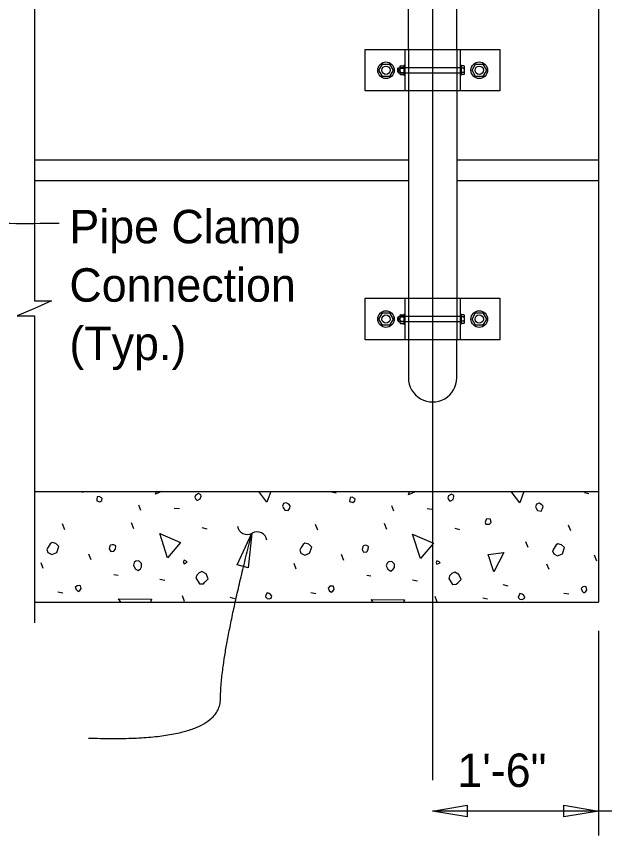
# Model space of a CAD drawing. Extents: x 0.5 to 39.7, y 0.9 to 25.6.
# Drawn here: x 23.735 to 27.279, y 12.062 to 17.001 of the extents above; entities that cross this region are included whole.
import ezdxf

# ---------------------------------------------------------------- set-up
doc = ezdxf.new("R2010")
doc.units = 0
for name, color, linetype in [('CL_Major', 7, 'Continuous'), ('Dimension', 7, 'Continuous'), ('Miscellaneous', 7, 'Continuous'), ('SteelMisc', 7, 'Continuous'), ('SteelMisc_h', 7, 'Continuous'), ('SupstrConc', 7, 'Continuous'), ('TextStructures', 7, 'Continuous')]:
    doc.layers.add(name, color=color, linetype=linetype)

msp = doc.modelspace()

# ---------------------------------------------------------------- linework, layer by layer
at = {"layer": 'CL_Major'}
msp.add_line((26.2429, 25.5043), (26.2429, 12.3953), dxfattribs=at)
at = {"layer": 'Dimension'}
for p, q in [((27.2429, 13.2961), (27.2429, 12.062)), ((28.5763, 12.21), (26.2429, 12.21))]:
    msp.add_line(p, q, dxfattribs=at)
msp.add_lwpolyline([(23.8431, 17.1361), (23.8431, 15.2855), (23.9464, 15.2855), (23.8431, 15.2405), (23.7397, 15.1955), (23.8431, 15.1955), (23.8431, 13.3448)], dxfattribs=at)
for points in [[(25.1546, 13.8857), (25.1324, 13.6757), (25.0644, 13.6947)], [(26.2429, 12.2101), (26.4512, 12.2454), (26.4512, 12.1748)], [(27.2429, 12.2101), (27.0347, 12.1748), (27.0347, 12.2454)]]:
    msp.add_lwpolyline(points, close=True, dxfattribs=at)
for centre, start, end in [((25.1255, 13.9368), 188.4294, 300.1567), ((25.1854, 13.8337), 8.4294, 120.1567)]:
    msp.add_arc(centre, 0.0596, start, end, dxfattribs=at)
for points in [[(23.9932, 15.7529), (23.0399, 15.7236), (23.3618, 16.2556), (23.4433, 16.5898), (22.9335, 16.6682), (22.6122, 16.6783)], [(24.1685, 12.6502), (24.964, 12.6205), (24.9656, 13.1567), (25.1547, 13.8855)]]:
    msp.add_open_spline(points, degree=2, dxfattribs=at)
at = {"layer": 'Miscellaneous'}
for p, q in [((26.0354, 16.6691), (26.0354, 16.6812)), ((26.0411, 16.6691), (26.0411, 16.6812)), ((26.0354, 15.1691), (26.0354, 15.1812)), ((26.0411, 15.1691), (26.0411, 15.1812)), ((24.1186, 14.1361), (24.1373, 14.1324)), ((25.6346, 14.1341), (25.6611, 14.1288)), ((27.1584, 14.1306), (27.185, 14.1253)), ((24.4856, 14.021), (24.4732, 14.0546)), ((24.6853, 14.0369), (24.7172, 14.0334)), ((26.0094, 14.0175), (25.997, 14.051)), ((26.2092, 14.0334), (26.241, 14.0298)), ((24.0277, 13.9061), (24.0136, 13.9414)), ((24.4432, 13.9114), (24.429, 13.9467)), ((25.5515, 13.9026), (25.5374, 13.9379)), ((25.967, 13.9079), (25.9528, 13.9432)), ((27.0754, 13.899), (27.0612, 13.9344)), ((24.8533, 13.9185), (24.8816, 13.9114)), ((26.3771, 13.9149), (26.4054, 13.9079)), ((26.819, 13.7983), (26.8049, 13.8336)), ((24.1851, 13.724), (24.1709, 13.7594)), ((25.7089, 13.7205), (25.6947, 13.7558)), ((27.2327, 13.7169), (27.2185, 13.7523)), ((23.8969, 13.6727), (23.8845, 13.7063)), ((25.4207, 13.6692), (25.4084, 13.7028)), ((26.9445, 13.6657), (26.9322, 13.6993)), ((24.3229, 13.6356), (24.3477, 13.6321)), ((25.8468, 13.6321), (25.8715, 13.6286)), ((24.5987, 13.6073), (24.6288, 13.602)), ((26.1225, 13.6038), (26.1526, 13.5985)), ((26.667, 13.5755), (26.6953, 13.5684)), ((23.9853, 13.5313), (24.0154, 13.526)), ((24.7472, 13.473), (24.7348, 13.5066)), ((25.0212, 13.4995), (25.0495, 13.4924)), ((25.5091, 13.5278), (25.5392, 13.5225)), ((26.271, 13.4695), (26.2587, 13.503)), ((26.545, 13.496), (26.5733, 13.4889)), ((27.0329, 13.5243), (27.063, 13.5189))]:
    msp.add_line(p, q, dxfattribs=at)
for points in [[(24.574, 14.12), (24.5789, 14.1361)], [(24.6099, 14.1361), (24.574, 14.12)], [(25.244, 14.0723), (25.1954, 14.1361)], [(25.2678, 14.1361), (25.244, 14.0723)], [(26.0978, 14.1165), (26.1038, 14.1361)], [(26.1416, 14.1361), (26.0978, 14.1165)], [(26.7678, 14.0687), (26.7165, 14.1361)], [(26.793, 14.1361), (26.7678, 14.0687)], [(24.2186, 14.0793), (24.2381, 14.074), (24.2505, 14.0829), (24.2522, 14.0952), (24.2487, 14.0988), (24.2346, 14.1058), (24.2222, 14.1041), (24.2204, 14.0917), (24.2186, 14.0793)], [(24.8215, 14.0846), (24.8285, 14.0846), (24.8427, 14.0917), (24.848, 14.1076), (24.8462, 14.1165), (24.8321, 14.1235), (24.8144, 14.1129), (24.8109, 14.1023), (24.8144, 14.0917), (24.8215, 14.0846)], [(25.7425, 14.0758), (25.7619, 14.0705), (25.7743, 14.0793), (25.7761, 14.0917), (25.7725, 14.0952), (25.7584, 14.1023), (25.746, 14.1005), (25.7442, 14.0882), (25.7425, 14.0758)], [(26.3453, 14.0811), (26.3523, 14.0811), (26.3665, 14.0882), (26.3718, 14.1041), (26.37, 14.1129), (26.3559, 14.12), (26.3382, 14.1094), (26.3347, 14.0988), (26.3382, 14.0882), (26.3453, 14.0811)], [(25.3429, 14.0404), (25.3518, 14.0245), (25.373, 14.021), (25.3818, 14.0369), (25.3854, 14.051), (25.3765, 14.0599), (25.3606, 14.0687), (25.3447, 14.0634), (25.3394, 14.0475), (25.3429, 14.0404)], [(26.8668, 14.0369), (26.8756, 14.021), (26.8968, 14.0175), (26.9057, 14.0334), (26.9092, 14.0475), (26.9004, 14.0564), (26.8844, 14.0652), (26.8685, 14.0599), (26.8632, 14.044), (26.8668, 14.0369)], [(26.5645, 13.9397), (26.5857, 13.9397), (26.5963, 13.9503), (26.591, 13.9697), (26.568, 13.9715), (26.5645, 13.9609), (26.5592, 13.9521), (26.5645, 13.9397), (26.5609, 13.9432)], [(24.6464, 13.7364), (24.5987, 13.8831), (24.7242, 13.8283), (24.6464, 13.7364)], [(26.1703, 13.7328), (26.1225, 13.8796), (26.248, 13.8248), (26.1703, 13.7328)], [(23.9252, 13.7682), (23.9482, 13.7558), (23.9782, 13.7682), (23.9906, 13.8053), (23.9729, 13.823), (23.9499, 13.8283), (23.9393, 13.8212), (23.927, 13.8018), (23.9181, 13.7859), (23.9252, 13.7682)], [(24.2947, 13.7912), (24.3035, 13.7753), (24.3229, 13.777), (24.3318, 13.7894), (24.3336, 13.8089), (24.3212, 13.8142), (24.3123, 13.8159), (24.3017, 13.8124), (24.2982, 13.8089), (24.2947, 13.7912)], [(25.449, 13.7647), (25.472, 13.7523), (25.502, 13.7647), (25.5144, 13.8018), (25.4967, 13.8195), (25.4738, 13.8248), (25.4632, 13.8177), (25.4508, 13.7983), (25.4419, 13.7823), (25.449, 13.7647)], [(25.8185, 13.7876), (25.8273, 13.7717), (25.8468, 13.7735), (25.8556, 13.7859), (25.8574, 13.8053), (25.845, 13.8106), (25.8362, 13.8124), (25.8255, 13.8089), (25.822, 13.8053), (25.8185, 13.7876)], [(26.9728, 13.7611), (26.9958, 13.7488), (27.0259, 13.7611), (27.0382, 13.7983), (27.0206, 13.8159), (26.9976, 13.8212), (26.987, 13.8142), (26.9746, 13.7947), (26.9658, 13.7788), (26.9728, 13.7611)], [(26.6122, 13.6515), (26.5786, 13.7558), (26.6723, 13.7682), (26.6122, 13.6515)], [(24.4396, 13.6922), (24.4502, 13.671), (24.4679, 13.6604), (24.482, 13.671), (24.4891, 13.6816), (24.4891, 13.7028), (24.4732, 13.7187), (24.4538, 13.7169), (24.4449, 13.7081), (24.4396, 13.6922)], [(24.7454, 13.701), (24.7649, 13.7099), (24.7578, 13.7169), (24.7454, 13.7222), (24.7401, 13.7099), (24.7454, 13.701)], [(25.9634, 13.6887), (25.974, 13.6674), (25.9917, 13.6568), (26.0059, 13.6674), (26.0129, 13.678), (26.0129, 13.6993), (25.997, 13.7152), (25.9776, 13.7134), (25.9687, 13.7046), (25.9634, 13.6887)], [(26.2693, 13.6975), (26.2887, 13.7063), (26.2816, 13.7134), (26.2693, 13.7187), (26.264, 13.7063), (26.2693, 13.6975)], [(24.8162, 13.6162), (24.8391, 13.5791), (24.8621, 13.5808), (24.871, 13.5897), (24.8904, 13.6091), (24.878, 13.6392), (24.8533, 13.6533), (24.8356, 13.6462), (24.8215, 13.6321), (24.8162, 13.6162)], [(26.34, 13.6126), (26.3629, 13.5755), (26.3859, 13.5773), (26.3948, 13.5861), (26.4142, 13.6056), (26.4018, 13.6356), (26.3771, 13.6498), (26.3594, 13.6427), (26.3453, 13.6286), (26.34, 13.6126)], [(24.0967, 13.5437), (24.1073, 13.5331), (24.1179, 13.5402), (24.125, 13.5508), (24.1214, 13.5684), (24.1126, 13.5702), (24.1002, 13.5684), (24.0896, 13.5578), (24.0967, 13.5437)], [(25.6205, 13.5402), (25.6311, 13.5296), (25.6417, 13.5366), (25.6488, 13.5472), (25.6452, 13.5649), (25.6364, 13.5667), (25.624, 13.5649), (25.6134, 13.5543), (25.6205, 13.5402)], [(27.1443, 13.5366), (27.1549, 13.526), (27.1655, 13.5331), (27.1726, 13.5437), (27.1691, 13.5614), (27.1602, 13.5631), (27.1478, 13.5614), (27.1372, 13.5508), (27.1443, 13.5366)], [(24.3642, 13.4695), (24.3495, 13.4889), (24.5492, 13.4871), (24.5426, 13.4695)], [(25.2457, 13.4907), (25.2581, 13.4889), (25.2705, 13.4942), (25.274, 13.5048), (25.2687, 13.5136), (25.2581, 13.5207), (25.2457, 13.526), (25.2386, 13.5119), (25.2351, 13.5013), (25.2457, 13.4907)], [(25.8854, 13.4695), (25.8733, 13.4854), (26.073, 13.4836), (26.0678, 13.4695)], [(26.7695, 13.4871), (26.7819, 13.4854), (26.7943, 13.4907), (26.7978, 13.5013), (26.7925, 13.5101), (26.7819, 13.5172), (26.7695, 13.5225), (26.7625, 13.5083), (26.7589, 13.4977), (26.7695, 13.4871)]]:
    msp.add_lwpolyline(points, dxfattribs=at)
at = {"layer": 'SteelMisc'}
for p, q in [((26.0971, 16.801), (26.0971, 17.2769)), ((26.3888, 16.801), (26.3888, 17.2769)), ((25.837, 16.801), (26.6489, 16.801)), ((25.837, 16.551), (25.837, 16.801)), ((26.0763, 16.801), (26.0763, 16.551)), ((26.4096, 16.801), (26.4096, 16.551)), ((26.6489, 16.801), (26.6489, 16.551)), ((26.0447, 16.6939), (26.0447, 16.6582)), ((26.0496, 16.702), (26.0697, 16.702)), ((26.0697, 16.7063), (26.0697, 16.6457)), ((26.0697, 16.7063), (26.0763, 16.7063)), ((26.0697, 16.702), (26.0697, 16.65)), ((26.4159, 16.7063), (26.4098, 16.7063)), ((26.4159, 16.7063), (26.4159, 16.6457)), ((26.4306, 16.702), (26.4159, 16.702)), ((26.4357, 16.6566), (26.4357, 16.6955)), ((26.0326, 16.684), (26.0382, 16.6906)), ((26.0326, 16.6663), (26.0326, 16.684)), ((26.0326, 16.6663), (26.0382, 16.6607)), ((26.0382, 16.6906), (26.0447, 16.6906)), ((26.0382, 16.6607), (26.0382, 16.6906)), ((26.0382, 16.6607), (26.0447, 16.6607)), ((26.0494, 16.689), (26.0697, 16.689)), ((26.0494, 16.6631), (26.0697, 16.6631)), ((26.0497, 16.65), (26.0697, 16.65)), ((26.0697, 16.6457), (26.0763, 16.6457)), ((26.4159, 16.6457), (26.4098, 16.6457)), ((26.4307, 16.689), (26.4159, 16.689)), ((26.4307, 16.663), (26.4159, 16.663)), ((26.4306, 16.65), (26.4159, 16.65)), ((26.6489, 16.551), (25.837, 16.551)), ((26.0971, 16.551), (26.0971, 15.301)), ((26.3888, 16.551), (26.3888, 15.301)), ((25.837, 15.301), (26.6489, 15.301)), ((25.837, 15.051), (25.837, 15.301)), ((26.0763, 15.301), (26.0763, 15.051)), ((26.4096, 15.301), (26.4096, 15.051)), ((26.6489, 15.301), (26.6489, 15.051)), ((26.0326, 15.184), (26.0382, 15.1906)), ((26.0326, 15.1663), (26.0326, 15.184)), ((26.0326, 15.1663), (26.0382, 15.1607)), ((26.0382, 15.1906), (26.0447, 15.1906)), ((26.0382, 15.1607), (26.0382, 15.1906)), ((26.0447, 15.1939), (26.0447, 15.1582)), ((26.0494, 15.189), (26.0697, 15.189)), ((26.0494, 15.1631), (26.0697, 15.1631)), ((26.0496, 15.202), (26.0697, 15.202)), ((26.0697, 15.2063), (26.0697, 15.1457)), ((26.0697, 15.2063), (26.0763, 15.2063)), ((26.0697, 15.202), (26.0697, 15.15)), ((26.4159, 15.2063), (26.4098, 15.2063)), ((26.4159, 15.2063), (26.4159, 15.1457)), ((26.4306, 15.202), (26.4159, 15.202)), ((26.4307, 15.189), (26.4159, 15.189)), ((26.4307, 15.163), (26.4159, 15.163)), ((26.4357, 15.1566), (26.4357, 15.1955)), ((26.0382, 15.1607), (26.0447, 15.1607)), ((26.0497, 15.15), (26.0697, 15.15)), ((26.0697, 15.1457), (26.0763, 15.1457)), ((26.4159, 15.1457), (26.4098, 15.1457)), ((26.4306, 15.15), (26.4159, 15.15)), ((26.6489, 15.051), (25.837, 15.051)), ((26.097, 15.051), (26.097, 14.8218)), ((26.3887, 14.8218), (26.3887, 15.051))]:
    msp.add_line(p, q, dxfattribs=at)
for points in [[(25.9403, 16.7135), (25.9836, 16.7135), (26.0053, 16.676), (25.9836, 16.6385), (25.9403, 16.6385), (25.9186, 16.676)], [(26.5023, 16.7135), (26.5456, 16.7135), (26.5673, 16.676), (26.5456, 16.6385), (26.5023, 16.6385), (26.4806, 16.676)], [(25.9403, 15.2135), (25.9836, 15.2135), (26.0053, 15.176), (25.9836, 15.1385), (25.9403, 15.1385), (25.9186, 15.176)], [(26.5023, 15.2135), (26.5456, 15.2135), (26.5673, 15.176), (26.5456, 15.1385), (26.5023, 15.1385), (26.4806, 15.176)]]:
    msp.add_lwpolyline(points, close=True, dxfattribs=at)
for centre, radius in [((25.962, 16.676), 0.05), ((25.962, 16.676), 0.025), ((26.5239, 16.676), 0.05), ((26.5239, 16.676), 0.025), ((25.962, 15.176), 0.05), ((26.5239, 15.176), 0.05), ((25.962, 15.176), 0.025), ((26.5239, 15.176), 0.025)]:
    msp.add_circle(centre, radius, dxfattribs=at)
for centre, radius, start, end in [((26.0513, 16.6955), 0.00674, 104.4891, 254.1889), ((26.4289, 16.6955), 0.00673, 285.7823, 75.5404), ((26.0642, 16.676), 0.0196, 138.628, 221.372), ((26.0513, 16.6565), 0.00673, 105.7823, 255.5404), ((26.4289, 16.6565), 0.00674, 284.4891, 74.1889), ((26.416, 16.676), 0.0196, 318.628, 41.372), ((26.0513, 15.1955), 0.00674, 104.4891, 254.1889), ((26.0642, 15.176), 0.0196, 138.628, 221.372), ((26.0513, 15.1565), 0.00673, 105.7823, 255.5404), ((26.4289, 15.1955), 0.00673, 285.7823, 75.5404), ((26.4289, 15.1565), 0.00674, 284.4891, 74.1889), ((26.416, 15.176), 0.0196, 318.628, 41.372)]:
    msp.add_arc(centre, radius, start, end, dxfattribs=at)
msp.add_ellipse((26.2429, 14.8218), major_axis=(0, 0.1458), ratio=0.999499, start_param=1.570796, end_param=4.712389, dxfattribs=at)
at = {"layer": 'SteelMisc_h'}
for p, q in [((26.0971, 16.801), (26.0971, 16.551)), ((26.3888, 16.801), (26.3888, 16.551)), ((26.4096, 16.6906), (26.0447, 16.6906)), ((26.0447, 16.6607), (26.4096, 16.6607)), ((26.0971, 15.301), (26.0971, 15.051)), ((26.3888, 15.301), (26.3888, 15.051)), ((26.4096, 15.1906), (26.0447, 15.1906)), ((26.0447, 15.1607), (26.4096, 15.1607))]:
    msp.add_line(p, q, dxfattribs=at)
at = {"layer": 'SupstrConc'}
for p, q in [((27.2429, 17.1361), (27.2429, 13.4695)), ((23.8431, 16.1361), (26.0971, 16.1361)), ((26.3888, 16.1361), (27.2428, 16.1361)), ((23.8431, 16.0111), (26.0971, 16.0111)), ((26.3888, 16.0111), (27.2428, 16.0111)), ((23.8431, 14.1361), (27.2429, 14.1361)), ((23.8431, 13.4695), (27.2429, 13.4695))]:
    msp.add_line(p, q, dxfattribs=at)

# ---------------------------------------------------------------- texts
at = {"layer": 'Dimension'}
for s, p in [('Pipe Clamp ', (24.0545, 15.6326)), ('Connection ', (24.0545, 15.2806)), ('(Typ.)', (24.0545, 14.9286))]:
    msp.add_text(s, height=0.2016, dxfattribs=at).set_placement(p)
at = {"layer": 'TextStructures'}
msp.add_text('1\'-6"', height=0.2016, dxfattribs=at).set_placement((26.3923, 12.3553))

doc.saveas('drawing.dxf')
